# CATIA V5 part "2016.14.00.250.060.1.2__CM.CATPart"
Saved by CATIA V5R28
Part number: 2016.14.00.250.060.1.2__CM
Property "id_number": "2016.14.00.250.060.1.2"
Publications: "Absolute Axis System", "driver", "slider", "base", "cam diagram"
Bounding box of the stored display mesh (mm): x -60 to 230, y -180 to 180, z 0 to 330
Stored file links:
  N:\B2\Normteile\K\2016\11-14\025\cm\2016.14.00.250.060.1.2__CM.CATPart
  H:\CAD_Startmodelle\Tests\fill-in_PRT-SL_TEMPLATE.xlsx
  H:\CAD_Startmodelle\V5-R24\R24_TEMPLATE_PRT_FIBRO_CAM_TECNOLOGIES_INDEX.xlsx
  H:\z_Einordnen\170511__Anfrage_TK_HN\170511__CC01_TKHN.CATPart
  N:\B2\Normteile\K\2016\9xxx\2016.9024.1705.001\Entwurf_\170511__CC01_TKHN.CATPart
  N:\B2\Normteile\K\2016\9xxx\2016.9024.1707.006\Konstruktion\2016.9024.1707.006__HP__CUSTOMIZED_CAM_CM.CATPart
  N:\B2\Normteile\K\2016\9xxx\2016.9024.1707.005\Konstruktion\2016.9024.1707.005__HP__CUSTOMIZED_CAM_CM.CATPart
  N:\B2\Normteile\K\2016\9xxx\2016.9024.1707.008\Konstruktion\2016.9024.1707.008__HP__CUSTOMIZED_CAM_CM.CATPart
  N:\B2\Normteile\K\2016\9xxx\2016.9024.1707.009\Konstruktion\2016.9024.1707.009__HP__CUSTOMIZED_CAM_CM.CATPart
  N:\B2\Normteile\K\2016\9xxx\2016.9024.1707.010\Konstruktion\2016.9024.1707.010__HP__CUSTOMIZED_CAM_CM.CATPart
  N:\B2\Normteile\K\2016\9xxx\2016.9024.1708.002\Konstruktion\2016.9024.1708.002__HP__CUSTOMIZED_CAM_CM.CATPart
  N:\B2\Normteile\K\2016\9xxx\2016.9024.1802.001\Konstruktion\2016.9024.1802.001__HP__CUSTOMIZED_CAM_CM.CATPart
  N:\B2\Normteile\K\2016\9xxx\2016.9024.1802.002\Konstruktion\2016.9024.1802.002__HP__CUSTOMIZED_CAM_CM.CATPart
  N:\B2\Normteile\K\2016\9xxx\2016.9024.1811.003\Konstruktion\2016.9024.1811.003__HP__CUSTOMIZED_CAM_CM.CATPart
  N:\B2\Normteile\K\2016\9xxx\2016.9015.1811.001\Konstruktion\am\2016.9015.1811.001__AM__FCC_HV_DMC_0125-00.CATPart
  N:\B2\Normteile\K\2016\9xxx\2016.9024.1811.009\Konstruktion\2016.9024.1811.009__HP__CUSTOMIZED_CAM_CM.CATPart
  N:\B2\Normteile\K\2016\9xxx\2016.9024.1911.002\Konstruktion\am\2016.9024.1911.002__AM__CUSTOMIZED_CAM_CM.CATPart
  N:\B2\Normteile\K\2016\9xxx\2016.9024.2002.006\Konstruktion\2016.9024.2002.006__AM.CATPart
  N:\B2\Normteile\K\2016\9xxx\2016.9024.2004.001\Konstruktion\2016.9024.2004.001__AM__FCC_HV_CAEC_0260-45.CATPart
  N:\B2\Normteile\K\2016\9xxx\2016.9024.2006.002\Konstruktion\2016.9024.2006.002__AM__FCC_HV_CAEC_0260-40.CATPart
  N:\B2\Normteile\K\2016\9xxx\2016.9024.2006.005\Konstruktion\am\2016.9024.2006.005__AM__CFCC_HV_AEPC_0080-65.CATPart
  N:\B2\Normteile\K\2016\9xxx\2016.9024.2006.004\Konstruktion\am\2016.9024.2006.004__AM__CFCC_HV_AEC_0210-35.CATPart
  N:\B2\Normteile\K\2016\9xxx\2016.9026.2006.001\Konstruktion\am\2016.9026.2006.001__AM__FCC_LV_CAEC_0180-40.CATPart
  N:\B2\Normteile\K\2016\9xxx\2016.9015.2007.001\Konstruktion\am\2016.9015.2007.001__AM__FCC_HV_CDMPC_0090-00.CATPart
  N:\B2\Normteile\K\2016\9xxx\2016.9024.2005.001\Konstruktion\am\2016.9024.2005.001__AM__CFCC_HV_AEPC_1400-70.CATPart
  N:\B2\Normteile\K\2016\9xxx\2016.9024.2007.004\Konstruktion\am\2016.9024.2007.004__AM__CFCC_HV_AEC_1250-80.CATPart
  N:\B2\Normteile\K\2016\11-14\005\2016.11.00.052.040.1.02__AS__DIE_MOUNT_CAM__W52_A0_S40.CATProduct
  N:\B2\Normteile\K\2016\11-14\015\2016.11.00.150.060.1.02__AS__DIE_MOUNT_CAM__W150_A0_S60.CATProduct
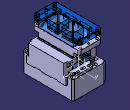
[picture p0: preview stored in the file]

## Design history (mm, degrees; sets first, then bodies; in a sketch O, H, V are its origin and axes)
Parameters
  group "process_parameters"
    modeltype = ""
    stocklist = ""
    id_number = "2016.14.00.250.060.1.2"
    id_number_rough_part = ""
    revision_index = ""
    revision_date = ""
    revision_description = ""
    category = ""
    material = ""
    manufacturing_information = ""
    standard = ""
  group "release_parameters_startmodel"
    sm_revision_index = "2016_00" {design table}
    sm_revision_date = "20.08.2016" {design table}
    sm_revision_name = "Meyer" {design table}
    sm_revision_description = "new part template FIBRO cam tecnologies" {design table}
AxisSystem1: origin (0, 0, 0), X (1, 0, 0), Y (0, 1, 0), Z (0, 0, 1)
Set1 "reference elements"
  Sketch1 "cam diagram" on ZX plane of AxisSystem1, origin (0, 0, 0), H (-1, 0, 0), V (0, 0, 1)
    line L1 (0, 0) -> (60, 0)
    line L2 (60, 0) -> (0, 60)
    point P2 (0, 60)
    line L3 (0, 60) -> (0, 0)
    length L1 = 60
    angle H L2 = 45
    horizontal: L1 H
    coincidence: P2 V
    vertical: L3 V
Body1 "finished_part" (main body)
  Body2 "rough_part"
  Add1 "rough_part": tool Body2
  Body3 "milling operations"
  Remove1 "milling operations": tool Body3
  Body4 "drilling operations"
  Remove2 "drilling operations": tool Body4
Body5 "driver"
  Solid1: solid without history
Body6 "slider"
  Solid2: solid without history
Body7 "base"
  Solid3: solid without history
Body8 "opened position"
  Body9 "slider"
    Body10 "slider"
      Solid4: linked copy from another document
    Assemble1: tool Body10
    Translate1: FirstPoint vertex [element of Sketch1 | element of Sketch1], SecondPoint vertex [element of Sketch1 | element of Sketch1], ToTransfor Assemble1
  Assemble2: tool Body9
  Body11 "driver"
    Body12 "driver"
      Solid5: linked copy from another document
    Assemble3: tool Body12
    Translate2: FirstPoint vertex [element of Sketch1 | element of Sketch1], SecondPoint vertex [element of Sketch1 | element of Sketch1], ToTransfor Assemble3
  Assemble4: tool Body11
